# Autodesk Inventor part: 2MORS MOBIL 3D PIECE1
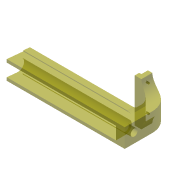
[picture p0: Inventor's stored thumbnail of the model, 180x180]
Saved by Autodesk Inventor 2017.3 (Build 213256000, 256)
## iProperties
Shininess: 20.0
Angle Display Precision: 2
Document Length Units: 11269
Document Angle Units: 11279
Document Time Units: 11290
Document Mass Units: 11283
Document Length Units Precision: 3
Document Angle Units Precision: 2
Created: 2002-04
Part Number: 2MORS MOBIL 3D PIECE1
Material: Acier doux
Document SubType Name: Modélisation
Designer: Administrateur
Density: 7.86 g/cm^3
Appearance: Jaune (transparent)
Density: 7.86
Volumn: 437.5054500699133
Area: 865.0708771001972
PropertySet Name: Model Information
Control State: 0
Master: False
Checked Out: False
Author: Administrateur
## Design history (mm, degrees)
sketch "Esquisse1"
  geometry: L1 (72.687, 153.898)-(72.687, 105.898); L2 (342.687, 153.898)-(72.687, 153.898); L3 (342.687, 105.898)-(342.687, 153.898); L4 (72.687, 105.898)-(342.687, 105.898)
  constraints: 8 end point, 2 horizontal, 2 vertical, 1 other
extrude "ExtrusionBorgne1" new body sketch "Esquisse1" distance "d0" = 43; taper "d1" = 0 deg
sketch "Esquisse2"
  geometry: L1 (7, 0)-(7, 21.5); L2 (36, 0)-(7, 0); L3 (36, 21.5)-(36, 0); A1 r 14.5 centre (21.5, 21.5) between (36, 21.5) and (7, 21.5)
  constraints: 6 end point, 2 point on circle, 2 tangent, 2 vertical, 1 centre point, 1 horizontal
  dimensions: "d10" = 21.5 distance of L3.start L2.start
extrude "ExtrusionBorgne2" cut sketch "Esquisse2" distance "d11" = 250; taper "d12" = 0 deg
sketch "Esquisse3"
  geometry: 1 further point
hole "AM_HOLE_0301DE_1" sketch "Esquisse3" diameter "d15" = 16; stored, may be unused: countersink angle "d19" = 82 deg, drill point angle "d21" = 118 deg; dims "d16" = 6, "d17" = 4, "d18" = 2, "d20" = 8
sketch "Esquisse5"
  geometry: L1 (72.687, 153.898)-(77.687, 153.898); L2 (72.687, 105.898)-(72.687, 153.898); L3 (77.687, 153.898)-(72.687, 105.898)
  constraints: 6 end point, 1 horizontal, 1 vertical
  dimensions: "d23" = 5 distance of L1.start L1.end
extrude "ExtrusionBorgne3" cut sketch "Esquisse5" distance "d24" = 43; taper "d25" = 0 deg
sketch "Esquisse6"
  geometry: L1 (76.244, 140.048)-(77.687, 153.898); L2 (298.687, 140.048)-(76.244, 140.048); L3 (293.687, 153.898)-(298.687, 140.048); L4 (77.687, 153.898)-(293.687, 153.898)
  constraints: 8 end point, 2 horizontal
extrude "ExtrusionBorgne4" join sketch "Esquisse6" distance "d26" = 2; taper "d27" = 0 deg
sketch "Esquisse7"
  geometry: L1 (-293.687, 153.898)-(-298.689, 138.866); L2 (-77.687, 153.898)-(-293.687, 153.898); L3 (-76.099, 138.866)-(-77.687, 153.898); L4 (-298.689, 138.866)-(-76.099, 138.866)
  constraints: 8 end point, 2 horizontal
extrude "ExtrusionBorgne5" join sketch "Esquisse7" distance "d28" = 2; taper "d29" = 0 deg
sketch "Esquisse8"
  geometry: L1 (317.687, 168.898)-(317.687, 153.898); L2 (317.687, 153.898)-(342.687, 153.898); L3 (342.687, 168.898)-(342.687, 153.898); L4 (294.687, 191.898)-(294.687, 216.898); A1 r 23 centre (294.687, 168.898) between (317.687, 168.898) and (294.687, 191.898); A2 r 48 centre (294.687, 168.898) between (342.687, 168.898) and (294.687, 216.898)
  constraints: 8 end point, 4 point on circle, 3 vertical, 2 centre point, 2 tangent, 1 concentric, 1 horizontal
  dimensions: "d31" = 15 distance of L2.end L3.start
extrude "ExtrusionBorgne6" join sketch "Esquisse8" distance "d32" = 43; taper "d33" = 0 deg
sketch "Esquisse9"
  geometry: L1 (-71.25, 25)-(-71.25, 0); L2 (28.25, 25)-(-71.25, 25); L3 (28.25, 0)-(28.25, 25); L4 (-71.25, 0)-(28.25, 0)
  constraints: 8 end point, 2 horizontal, 2 vertical
  dimensions: "d36" = 99.5 distance of L1.start L2.start; "d38" = 25 distance of L1.start L1.end
extrude "ExtrusionBorgne7" join sketch "Esquisse9" distance "d39" = 15; taper "d40" = 0 deg
sketch "Esquisse10"
  geometry: L1 (-71.25, 10)-(-71.25, 25); L2 (28.25, 10)-(-71.25, 10); L3 (28.25, 25)-(28.25, 10); L4 (-71.25, 25)-(28.25, 25)
  constraints: 8 end point, 2 horizontal, 2 vertical
extrude "ExtrusionBorgne8" cut sketch "Esquisse10" distance "d42" = 5; taper "d43" = 0 deg
sketch "Esquisse11"
  geometry: 1 further point
sketch "Esquisse12"
  geometry: 1 further point
hole "AM_HOLE_SI0029_1" sketch "Esquisse11" diameter "d47" = 4.13398; stored, may be unused: countersink angle "d51" = 82 deg, drill point angle "d53" = 118 deg; dims "d48" = 10, "d49" = 4, "d50" = 2, "d52" = 13.2
fillet "Congé Arrondi1" dims "d54" = 5
sketch "Esquisse14"
  geometry: L1 (28.25, 25)-(28.25, 10) reference; L2 (-71.25, 25)-(28.25, 25) reference; L3 (-71.25, 10)-(-71.25, 25) reference; 2 further points
  dimensions: "d55" = 19.45 distance from line of point (-51.8, 19.75) L3; "d56" = 19.45 distance from line of L1 point (8.8, 19.75) (= d55); "d57" = 5.25 distance from line of L2 point (-51.8, 19.75); "d58" = 5.25 distance from line of L2 point (8.8, 19.75) (= d57)
hole "Perçage3" sketch "Esquisse14" at (-51.8, 19.75), (8.8, 19.75) diameter "d59" = 4.134; stored, may be unused: countersink angle "d63" = 82 deg, drill point angle "d65" = 118 deg; dims "d60" = 6, "d61" = 4, "d62" = 2, "d64" = 8
fillet "Congé2" dims "d66" = 30
fillet "Congé3" dims "d67" = 30
node "Solide1"
node "Corps solides"
node "Corps surfaciques"
other parameters: "d2" = 0, "d3" = 0, "d4" = 0, "d5" = 0, "d6" = 0, "d7" = 0, "d8" = 0, "d9" = 21.5 (derived), "d13" = 0, "d14" = 0, "d22" = 5 (derived), "d30" = 15 (derived), "d34" = 0, "d35" = 99.5 (derived), "d37" = 25 (derived), "d41" = 0, "d44" = 0, "d45" = 0, "d46" = 0
